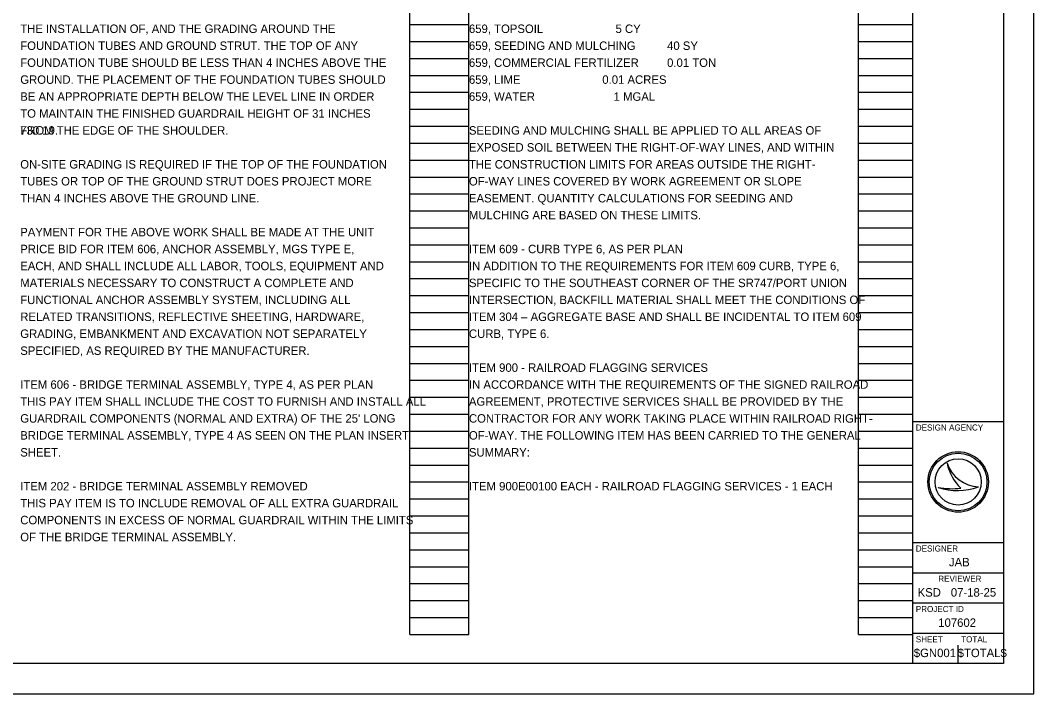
# Model space of a CAD drawing. Extents: x 31.7 to 83.9, y -7.4 to 14.6.
# Drawn here: x 67.17 to 83.93, y -7.39 to 3.74 of the extents above; entities that cross this region are included whole.
import ezdxf

# ---------------------------------------------------------------- set-up
doc = ezdxf.new("R2010")
doc.units = 0
for name, color, linetype in [('SH_Border', 7, 'Continuous'), ('SH_Cut_Line', 7, 'Continuous'), ('SH_Data', 7, 'Continuous'), ('SH_Text', 7, 'Continuous')]:
    doc.layers.add(name, color=color, linetype=linetype)

msp = doc.modelspace()

# ---------------------------------------------------------------- linework, layer by layer
at = {"layer": 'SH_Border'}
for p, q in [((81.926, -6.89), (81.926, 14.11)), ((81.926, -2.89), (83.426, -2.89)), ((81.926, -4.89), (83.426, -4.89)), ((81.926, -5.39), (83.426, -5.39)), ((81.926, -5.89), (83.426, -5.89)), ((81.926, -6.39), (83.426, -6.39))]:
    msp.add_line(p, q, dxfattribs=at)
msp.add_lwpolyline([(51.426, 14.11), (83.426, 14.11), (83.426, -6.89), (51.426, -6.89)], close=True, dxfattribs=at)
at = {"layer": 'SH_Cut_Line'}
msp.add_lwpolyline([(49.926, -7.39), (83.926, -7.39), (83.926, 14.61), (49.926, 14.61)], close=True, dxfattribs=at)
at = {"layer": 'SH_Data'}
for p, q in [((73.606, -6.41), (73.606, 13.75)), ((74.586, -6.41), (74.586, 13.75)), ((81.026, -6.41), (81.026, 13.75)), ((81.926, -6.41), (81.926, 13.75)), ((73.606, 3.67), (74.586, 3.67)), ((81.026, 3.67), (81.926, 3.67)), ((73.606, 3.39), (74.586, 3.39)), ((81.026, 3.39), (81.926, 3.39)), ((73.606, 3.11), (74.586, 3.11)), ((81.026, 3.11), (81.926, 3.11)), ((73.606, 2.83), (74.586, 2.83)), ((81.026, 2.83), (81.926, 2.83)), ((73.606, 2.55), (74.586, 2.55)), ((81.026, 2.55), (81.926, 2.55)), ((73.606, 2.27), (74.586, 2.27)), ((81.026, 2.27), (81.926, 2.27)), ((73.606, 1.99), (74.586, 1.99)), ((81.026, 1.99), (81.926, 1.99)), ((73.606, 1.71), (74.586, 1.71)), ((81.026, 1.71), (81.926, 1.71)), ((73.606, 1.43), (74.586, 1.43)), ((81.026, 1.43), (81.926, 1.43)), ((73.606, 1.15), (74.586, 1.15)), ((81.026, 1.15), (81.926, 1.15)), ((73.606, 0.87), (74.586, 0.87)), ((81.026, 0.87), (81.926, 0.87)), ((73.606, 0.59), (74.586, 0.59)), ((81.026, 0.59), (81.926, 0.59)), ((73.606, 0.31), (74.586, 0.31)), ((81.026, 0.31), (81.926, 0.31)), ((73.606, 0.03), (74.586, 0.03)), ((81.026, 0.03), (81.926, 0.03)), ((73.606, -0.25), (74.586, -0.25)), ((81.026, -0.25), (81.926, -0.25)), ((73.606, -0.53), (74.586, -0.53)), ((81.026, -0.53), (81.926, -0.53)), ((73.606, -0.81), (74.586, -0.81)), ((81.026, -0.81), (81.926, -0.81)), ((73.606, -1.09), (74.586, -1.09)), ((81.026, -1.09), (81.926, -1.09)), ((73.606, -1.37), (74.586, -1.37)), ((81.026, -1.37), (81.926, -1.37)), ((73.606, -1.65), (74.586, -1.65)), ((81.026, -1.65), (81.926, -1.65)), ((73.606, -1.93), (74.586, -1.93)), ((81.026, -1.93), (81.926, -1.93)), ((73.606, -2.21), (74.586, -2.21)), ((81.026, -2.21), (81.926, -2.21)), ((73.606, -2.49), (74.586, -2.49)), ((81.026, -2.49), (81.926, -2.49)), ((73.606, -2.77), (74.586, -2.77)), ((81.026, -2.77), (81.926, -2.77)), ((73.606, -3.05), (74.586, -3.05)), ((81.026, -3.05), (81.926, -3.05)), ((73.606, -3.33), (74.586, -3.33)), ((81.026, -3.33), (81.926, -3.33)), ((73.606, -3.61), (74.586, -3.61)), ((81.026, -3.61), (81.926, -3.61)), ((82.494, -3.58), (82.494, -3.58)), ((73.606, -3.89), (74.586, -3.89)), ((81.026, -3.89), (81.926, -3.89)), ((82.343, -3.98), (82.343, -3.98)), ((82.676, -3.89), (82.676, -3.89)), ((83.013, -3.971), (83.013, -3.971)), ((73.606, -4.17), (74.586, -4.17)), ((81.026, -4.17), (81.926, -4.17)), ((73.606, -4.45), (74.586, -4.45)), ((81.026, -4.45), (81.926, -4.45)), ((73.606, -4.73), (74.586, -4.73)), ((81.026, -4.73), (81.926, -4.73)), ((73.606, -5.01), (74.586, -5.01)), ((81.026, -5.01), (81.926, -5.01)), ((73.606, -5.29), (74.586, -5.29)), ((81.026, -5.29), (81.926, -5.29)), ((73.606, -5.57), (74.586, -5.57)), ((81.026, -5.57), (81.926, -5.57)), ((73.606, -5.85), (74.586, -5.85)), ((81.026, -5.85), (81.926, -5.85)), ((73.606, -6.13), (74.586, -6.13)), ((81.026, -6.13), (81.926, -6.13)), ((73.606, -6.41), (74.586, -6.41)), ((81.026, -6.41), (81.926, -6.41)), ((82.676, -6.89), (82.676, -6.59)), ((82.301, -6.715), (82.301, -6.715))]:
    msp.add_line(p, q, dxfattribs=at)
for radius in [0.5, 0.477, 0.477, 0.382]:
    msp.add_circle((82.676, -3.89), radius, dxfattribs=at)
for centre, radius, start, end in [((83.042, -3.392), 0.58, 198.9257, 198.9319), ((83.273, -3.42), 0.796, 191.6379, 191.6421), ((83.042, -3.392), 0.58, 198.9319, 267.1657), ((83.273, -3.42), 0.796, 191.6421, 226.0947), ((82.666, -3.02), 1.013, 251.4576, 290.0832), ((82.574, -2.735), 1.266, 259.4964, 259.4995), ((82.666, -3.02), 1.013, 251.4527, 251.4576), ((82.574, -2.735), 1.266, 259.4995, 276.6672)]:
    msp.add_arc(centre, radius, start, end, dxfattribs=at)

# ---------------------------------------------------------------- texts
for s, height, p in [('DESIGN AGENCY', 0.1, (81.976, -3.04)), ('DESIGNER', 0.1, (81.976, -5.04)), ('JAB', 0.14, (82.524, -5.285)), ('REVIEWER', 0.1, (82.348, -5.54)), ('KSD', 0.14, (82.006, -5.785)), ('07-18-25', 0.14, (82.555, -5.785)), ('PROJECT ID', 0.1, (81.976, -6.04)), ('107602', 0.14, (82.347, -6.285)), ('SHEET', 0.1, (81.976, -6.54)), ('TOTAL', 0.1, (82.726, -6.54)), ('$GN001', 0.14, (81.943, -6.785)), ('$TOTAL$', 0.14, (82.669, -6.785))]:
    msp.add_text(s, height=height, dxfattribs=at).set_placement(p)
at = {"layer": 'SH_Text'}
for s, p in [('THE INSTALLATION OF, AND THE GRADING AROUND THE', (67.166, 3.53)), ('659, TOPSOIL                       5 CY', (74.586, 3.53)), ('FOUNDATION TUBES AND GROUND STRUT. THE TOP OF ANY', (67.166, 3.25)), ('659, SEEDING AND MULCHING          40 SY', (74.586, 3.25)), ('FOUNDATION TUBE SHOULD BE LESS THAN 4 INCHES ABOVE THE', (67.166, 2.97)), ('659, COMMERCIAL FERTILIZER         0.01 TON', (74.586, 2.97)), ('GROUND. THE PLACEMENT OF THE FOUNDATION TUBES SHOULD', (67.166, 2.69)), ('659, LIME                          0.01 ACRES', (74.586, 2.69)), ('BE AN APPROPRIATE DEPTH BELOW THE LEVEL LINE IN ORDER', (67.166, 2.41)), ('659, WATER                         1 MGAL', (74.586, 2.41)), ('TO MAINTAIN THE FINISHED GUARDRAIL HEIGHT OF 31 INCHES', (67.166, 2.13)), ('730.19.', (67.166, 1.85)), ('FROM THE EDGE OF THE SHOULDER.', (67.166, 1.85)), ('SEEDING AND MULCHING SHALL BE APPLIED TO ALL AREAS OF', (74.586, 1.85)), ('EXPOSED SOIL BETWEEN THE RIGHT-OF-WAY LINES, AND WITHIN', (74.586, 1.57)), ('ON-SITE GRADING IS REQUIRED IF THE TOP OF THE FOUNDATION', (67.166, 1.29)), ('THE CONSTRUCTION LIMITS FOR AREAS OUTSIDE THE RIGHT-', (74.586, 1.29)), ('TUBES OR TOP OF THE GROUND STRUT DOES PROJECT MORE', (67.166, 1.01)), ('OF-WAY LINES COVERED BY WORK AGREEMENT OR SLOPE', (74.586, 1.01)), ('THAN 4 INCHES ABOVE THE GROUND LINE.', (67.166, 0.73)), ('EASEMENT. QUANTITY CALCULATIONS FOR SEEDING AND', (74.586, 0.73)), ('MULCHING ARE BASED ON THESE LIMITS.', (74.586, 0.45)), ('PAYMENT FOR THE ABOVE WORK SHALL BE MADE AT THE UNIT', (67.166, 0.17)), ('PRICE BID FOR ITEM 606, ANCHOR ASSEMBLY, MGS TYPE E,', (67.166, -0.11)), ('ITEM 609 - CURB TYPE 6, AS PER PLAN', (74.586, -0.11)), ('EACH, AND SHALL INCLUDE ALL LABOR, TOOLS, EQUIPMENT AND', (67.166, -0.39)), ('IN ADDITION TO THE REQUIREMENTS FOR ITEM 609 CURB, TYPE 6, ', (74.586, -0.39)), ('MATERIALS NECESSARY TO CONSTRUCT A COMPLETE AND', (67.166, -0.67)), ('SPECIFIC TO THE SOUTHEAST CORNER OF THE SR747/PORT UNION ', (74.586, -0.67)), ('FUNCTIONAL ANCHOR ASSEMBLY SYSTEM, INCLUDING ALL', (67.166, -0.95)), ('INTERSECTION, BACKFILL MATERIAL SHALL MEET THE CONDITIONS OF ', (74.586, -0.95)), ('RELATED TRANSITIONS, REFLECTIVE SHEETING, HARDWARE,', (67.166, -1.23)), ('ITEM 304 – AGGREGATE BASE AND SHALL BE INCIDENTAL TO ITEM 609 ', (74.586, -1.23)), ('GRADING, EMBANKMENT AND EXCAVATION NOT SEPARATELY', (67.166, -1.51)), ('CURB, TYPE 6.', (74.586, -1.51)), ('SPECIFIED, AS REQUIRED BY THE MANUFACTURER.', (67.166, -1.79)), ('ITEM 900 - RAILROAD FLAGGING SERVICES', (74.586, -2.07)), ('ITEM 606 - BRIDGE TERMINAL ASSEMBLY, TYPE 4, AS PER PLAN', (67.166, -2.35)), ('IN ACCORDANCE WITH THE REQUIREMENTS OF THE SIGNED RAILROAD ', (74.586, -2.35)), ('THIS PAY ITEM SHALL INCLUDE THE COST TO FURNISH AND INSTALL ALL ', (67.166, -2.63)), ('AGREEMENT, PROTECTIVE SERVICES SHALL BE PROVIDED BY THE ', (74.586, -2.63)), ("GUARDRAIL COMPONENTS (NORMAL AND EXTRA) OF THE 25' LONG ", (67.166, -2.91)), ('CONTRACTOR FOR ANY WORK TAKING PLACE WITHIN RAILROAD RIGHT-', (74.586, -2.91)), ('BRIDGE TERMINAL ASSEMBLY, TYPE 4 AS SEEN ON THE PLAN INSERT ', (67.166, -3.19)), ('OF-WAY. THE FOLLOWING ITEM HAS BEEN CARRIED TO THE GENERAL ', (74.586, -3.19)), ('SHEET. ', (67.166, -3.47)), ('SUMMARY:', (74.586, -3.47)), ('ITEM 202 - BRIDGE TERMINAL ASSEMBLY REMOVED', (67.166, -4.03)), ('ITEM 900E00100 EACH - RAILROAD FLAGGING SERVICES - 1 EACH', (74.586, -4.03)), ('THIS PAY ITEM IS TO INCLUDE REMOVAL OF ALL EXTRA GUARDRAIL ', (67.166, -4.31)), ('COMPONENTS IN EXCESS OF NORMAL GUARDRAIL WITHIN THE LIMITS ', (67.166, -4.59)), ('OF THE BRIDGE TERMINAL ASSEMBLY. ', (67.166, -4.87))]:
    msp.add_text(s, height=0.14, dxfattribs=at).set_placement(p)

doc.saveas('drawing.dxf')
